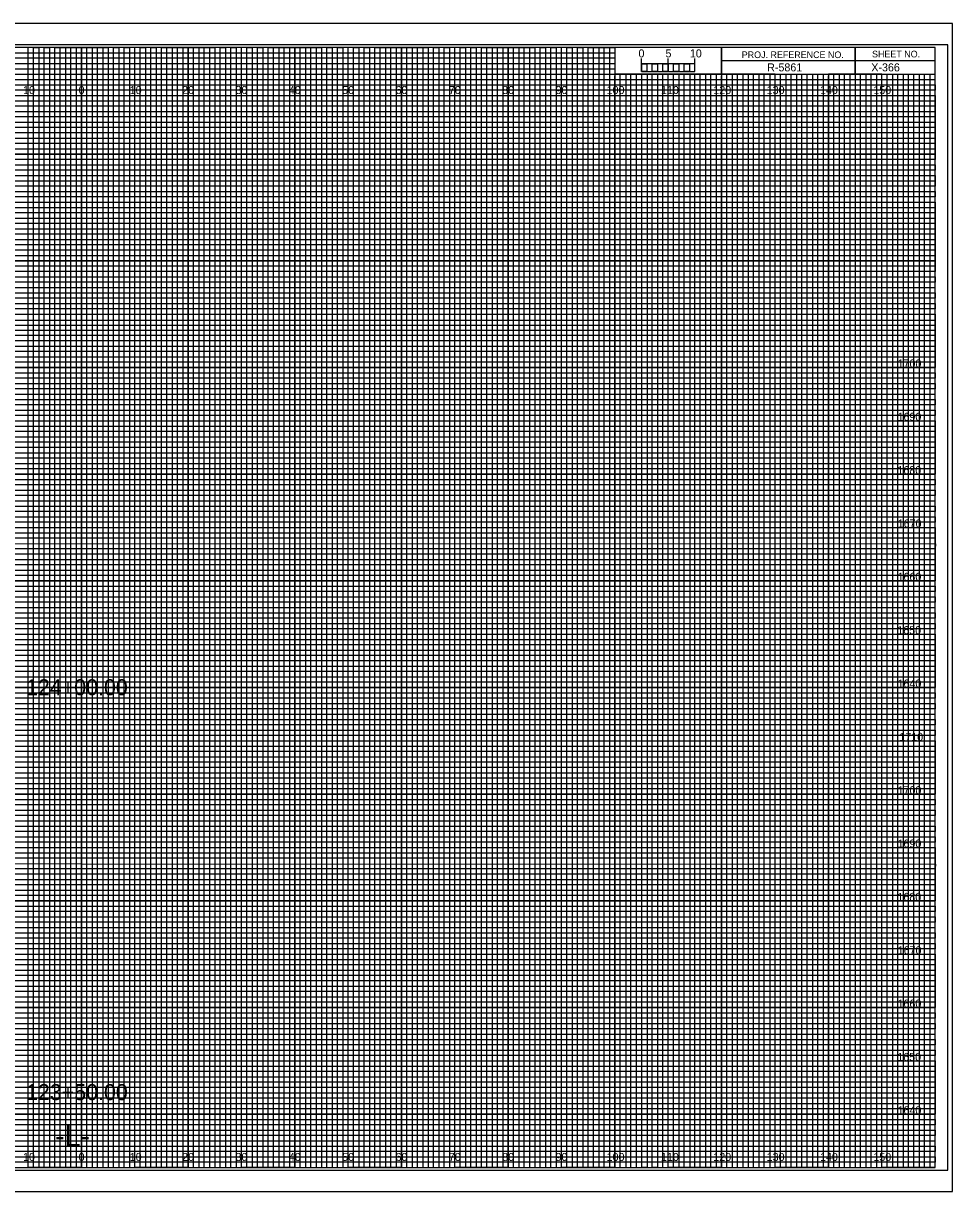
# Model space of a CAD drawing. Extents: x -13 to 323, y -5 to 2414.
# Drawn here: x 149.1 to 323.3, y 435.5 to 654.5 of the extents above; entities that cross this region are included whole.
import ezdxf

# ---------------------------------------------------------------- set-up
doc = ezdxf.new("R2010")
doc.units = 0
for name, color, linetype in [('Prop XS Alignment Label', 7, 'Continuous'), ('Prop XS Bar Scale Labels', 7, 'Continuous'), ('Prop XS Elevation Labels', 7, 'Continuous'), ('Prop XS Offset Labels', 7, 'Continuous'), ('Prop XS Project Number', 7, 'Continuous'), ('Prop XS Sheet Number', 7, 'Continuous'), ('Prop XS Station Labels', 7, 'Continuous'), ('Sheet Cross Section CELL', 7, 'Continuous'), ('Sheet Cross Section Grid Major CELL', 7, 'Continuous'), ('Sheet Cross Section Grid Middle CELL', 7, 'Continuous'), ('Sheet Cross Section Grid Minor 1 CELL', 7, 'Continuous'), ('Sheet Cross Section Grid Minor 2 CELL', 7, 'Continuous'), ('Sheet Cross Section Scale CELL', 7, 'Continuous'), ('Sheet Cutting Line CELL', 7, 'Continuous'), ('Sheet DOT Grid CELL', 7, 'Continuous'), ('Sheet Plot Border Inside CELL', 7, 'Continuous'), ('Sheet Plot Border Outside CELL', 7, 'Continuous')]:
    doc.layers.add(name, color=color, linetype=linetype)

msp = doc.modelspace()

# ---------------------------------------------------------------- linework, layer by layer
at = {"layer": 'Sheet Cross Section CELL'}
for p, q in [((305, 650), (305, 645)), ((305, 645), (305, 650)), ((280, 647.5), (280, 645)), ((320, 647.49), (280, 647.49)), ((280, 645), (320, 645))]:
    msp.add_line(p, q, dxfattribs=at)
for points in [[(320, 650), (0, 650), (0, 440), (320, 440)], [(280, 650), (260, 650), (260, 645.03), (280, 645.03)], [(320, 650), (280, 650), (280, 645), (320, 645)]]:
    msp.add_lwpolyline(points, close=True, dxfattribs=at)
at = {"layer": 'Sheet Cross Section Grid Major CELL'}
for p, q in [((150, 650), (140, 650)), ((150, 440), (150, 650)), ((170, 650), (160, 650)), ((160, 650), (160, 440)), ((170, 440), (170, 650)), ((190, 650), (180, 650)), ((180, 650), (180, 440)), ((190, 440), (190, 650)), ((210, 650), (200, 650)), ((200, 650), (200, 440)), ((210, 440), (210, 650)), ((230, 650), (220, 650)), ((220, 650), (220, 440)), ((230, 440), (230, 650)), ((250, 650), (240, 650)), ((240, 650), (240, 440)), ((250, 440), (250, 650)), ((260, 650), (260, 440)), ((270, 440), (270, 645)), ((290, 645), (280, 645)), ((280, 645), (280, 440)), ((290, 440), (290, 645)), ((310, 645), (300, 645)), ((300, 645), (300, 440)), ((310, 440), (310, 645)), ((160, 440), (150, 440)), ((180, 440), (170, 440)), ((200, 440), (190, 440)), ((220, 440), (210, 440)), ((240, 440), (230, 440)), ((260, 440), (250, 440)), ((280, 440), (270, 440)), ((300, 440), (290, 440)), ((320, 440), (310, 440)), ((320, 440), (320, 440))]:
    msp.add_line(p, q, dxfattribs=at)
for points in [[(0, 640), (320, 640), (320, 630), (0, 630)], [(0, 620), (320, 620), (320, 610), (0, 610)], [(0, 600), (320, 600), (320, 590), (0, 590)], [(0, 580), (320, 580), (320, 570), (0, 570)], [(0, 560), (320, 560), (320, 550), (0, 550)], [(0, 540), (320, 540), (320, 530), (0, 530)], [(0, 520), (320, 520), (320, 510), (0, 510)], [(0, 500), (320, 500), (320, 490), (0, 490)], [(0, 480), (320, 480), (320, 470), (0, 470)], [(0, 460), (320, 460), (320, 450), (0, 450)]]:
    msp.add_lwpolyline(points, dxfattribs=at)
at = {"layer": 'Sheet Cross Section Grid Middle CELL'}
for points in [[(145, 440), (155, 440), (155, 650), (165, 650), (165, 440), (175, 440), (175, 650), (185, 650), (185, 440), (195, 440), (195, 650), (205, 650), (205, 440), (215, 440), (215, 650), (225, 650), (225, 440), (235, 440), (235, 650), (245, 650), (245, 440), (255, 440), (255, 650), (259.93, 650), (260, 650), (260, 645), (264.99, 645), (264.99, 440), (275, 440), (275, 645), (285, 645), (285, 440), (295, 440), (295, 645), (305, 645), (305, 440), (315, 440), (315, 645)], [(0, 645), (275, 645)], [(0, 625), (320, 625), (320, 635), (0, 635)], [(0, 605), (320, 605), (320, 615), (0, 615)], [(0, 585), (320, 585), (320, 595), (0, 595)], [(0, 565), (320, 565), (320, 575), (0, 575)], [(0, 545), (320, 545), (320, 555), (0, 555)], [(0, 525), (320, 525), (320, 535), (0, 535)], [(0, 505), (320, 505), (320, 515), (0, 515)], [(0, 485), (320, 485), (320, 495), (0, 495)], [(0, 465), (320, 465), (320, 475), (0, 475)], [(0, 445), (320, 445), (320, 455), (0, 455)]]:
    msp.add_lwpolyline(points, dxfattribs=at)
at = {"layer": 'Sheet Cross Section Grid Minor 1 CELL'}
for p, q in [((0, 649), (260, 649)), ((260, 649), (260, 647.98)), ((260, 647.98), (0, 647.98)), ((0, 647), (260, 647)), ((260, 647), (260, 645.89)), ((260, 645.89), (0, 645.89)), ((0, 644), (320, 644))]:
    msp.add_line(p, q, dxfattribs=at)
for points in [[(0, 643), (270, 643), (320, 643), (320, 642), (0, 642)], [(0, 641), (320, 641), (320, 639), (0, 639)], [(0, 638), (320, 638), (320, 637), (0, 636.98)], [(0, 636), (320, 636), (320, 634), (0, 634)], [(0, 633), (320, 633), (320, 632), (0, 632)], [(0, 631), (320, 631), (320, 629), (0, 629)], [(0, 628), (320, 628), (320, 627), (0, 627)], [(0, 626), (320, 626), (320, 624), (0, 624)], [(0, 623), (320, 623), (320, 622), (0, 622)], [(0, 621), (320, 621), (320, 619), (0, 619)], [(0, 618), (320, 618), (320, 617), (0, 617)], [(0, 616), (320, 616), (320, 613.95), (320, 613), (320, 612), (0, 612)], [(0, 614), (320, 614), (320, 613), (0, 613)], [(0, 611), (320, 611), (320, 609), (0, 609.03)], [(0, 609.03), (320, 609), (320, 608), (0, 608)], [(0, 607), (320, 607), (320, 606), (0, 606)], [(0, 604), (320, 604), (320, 603), (0, 603)], [(0, 602), (320, 602), (320, 601), (0, 601)], [(-0.07, 598.89), (320, 598.89), (320, 597.88), (-0.07, 597.88)], [(0, 597), (320, 597), (320, 596), (0, 596)], [(0, 594), (320, 594), (320, 593), (0, 593)], [(0, 592), (320, 592), (320, 591), (0, 591)], [(0, 589), (320, 589), (320, 588), (0, 588)], [(0, 587), (320, 587), (320, 586), (0, 586)], [(0, 584), (320, 584), (320, 583), (0, 583)], [(0, 582), (320, 582), (320, 581), (0, 581)], [(0, 579), (320, 579), (319.99, 577.98), (0, 578)], [(0, 577), (320, 577), (320, 576), (0, 576)], [(0, 574), (320, 574), (320, 573), (0, 573)], [(0, 572), (320, 572), (320, 571), (0, 571)], [(0, 569), (320, 569), (320, 568), (0, 568)], [(0, 567), (320, 567), (320, 566), (0, 566)], [(0, 564), (320, 564), (320, 563), (0, 563)], [(0, 562), (320, 562), (320, 561), (0, 561)], [(0, 559), (320, 559), (320, 558), (0, 558)], [(0, 556.99), (320.07, 556.91), (320, 556), (0, 556)], [(0, 554), (320, 554), (320, 553), (0, 553)], [(0, 552), (320, 552), (320, 551), (0, 551)], [(0, 549), (320, 549), (320, 548), (0, 548)], [(0, 547), (320, 547), (320, 546), (0, 546)], [(0, 544), (320, 544), (320, 543), (0, 543)], [(0, 542), (320, 542), (320, 541), (0, 541)], [(0, 539), (320, 539), (320, 538), (0, 538)], [(0, 537), (320, 537), (320, 536), (0, 536)], [(0, 534), (320, 534), (320, 533), (0, 533)], [(0, 532), (320, 532), (320, 531), (0, 531)], [(0, 529), (320, 529), (320, 528), (0, 528)], [(0, 527), (320, 527), (320, 526), (0, 526)], [(0, 524), (320, 524), (320, 523), (0, 523)], [(0, 522), (320, 522), (320, 521), (0, 521)], [(0, 519), (320, 519), (319.99, 517.98), (0, 518)], [(0, 517), (320, 517), (320, 516), (0, 516)], [(0, 514), (320, 514), (320, 513), (0, 513)], [(0, 512), (320, 512), (320, 511), (0, 511)], [(0, 509), (320, 509), (320, 508), (0, 508)], [(0, 507), (320, 507), (320, 506), (0, 506)], [(0, 504), (320, 504), (320, 503), (0, 503)], [(0, 502), (320, 502), (320, 501), (0, 501)], [(0, 499), (320, 499), (320, 498), (0, 498)], [(0, 496.99), (320.07, 496.91), (320, 496), (0, 496)], [(0, 494), (320, 494), (320, 493), (0, 493)], [(0, 492), (320, 492), (320, 491), (0, 491)], [(0, 489), (320, 489), (320, 488), (0, 488)], [(0, 487), (320, 487), (320, 486), (0, 486)], [(0, 484), (320, 484), (320, 483), (0, 483)], [(0, 482), (320, 482), (320, 481), (0, 481)], [(0, 479), (320, 479), (320, 478), (0, 478)], [(0, 477), (320, 477), (320, 476), (0, 476)], [(0, 474), (320, 474), (320, 473), (0, 473)], [(0, 472), (320, 472), (320, 471), (0, 471)], [(0, 469), (320, 469), (320, 468), (0, 468)], [(0, 467), (320, 467), (320, 466), (0, 466)], [(0, 464), (320, 464), (320, 463), (0, 463)], [(0, 462), (320, 462), (320, 461), (0, 461)], [(0, 459), (320, 459), (320, 458), (0, 458)], [(0, 457), (320, 457), (320, 456), (0, 456)], [(0, 454), (320, 454), (320, 453), (0, 453)], [(0, 452), (320, 452), (320, 451), (0, 451)], [(0, 449), (320, 449), (320, 448), (0, 448)], [(0, 447), (320, 447), (320, 446), (0, 446)], [(0, 444), (320, 444), (320, 443), (0, 443)], [(0, 442), (320, 442), (320, 441), (0, 441)]]:
    msp.add_lwpolyline(points, dxfattribs=at)
at = {"layer": 'Sheet Cross Section Grid Minor 2 CELL'}
for p, q in [((267, 645), (266.01, 645)), ((266.01, 645), (266.01, 440)), ((267, 440), (267, 645)), ((269, 645), (268, 645)), ((268, 645), (268, 440)), ((269, 440), (269, 645)), ((266.01, 440), (265, 440)), ((268, 440), (267, 440))]:
    msp.add_line(p, q, dxfattribs=at)
for points in [[(150, 440), (151, 440), (151, 650), (152, 650), (152, 440)], [(152, 440), (153, 440), (153, 650), (154, 650), (154, 440)], [(155, 440), (156, 440), (156, 650), (157, 650), (157, 440)], [(157, 440), (158, 440), (158, 650), (159, 650), (159, 440)], [(160, 440), (161, 440), (161, 650), (162, 650), (162, 440)], [(162, 440), (163, 440), (163, 650), (164, 650), (164, 440)], [(165, 440), (166, 440), (166, 650), (167, 650), (167, 440)], [(167, 440), (168, 440), (168, 650), (169, 650), (169, 440)], [(170, 440), (171, 440), (171, 650), (172, 650), (172, 440)], [(172, 440), (173, 440), (173, 650), (174, 650), (174, 440)], [(175, 440), (176, 440), (176, 650), (177, 650), (177, 440)], [(177, 440), (178, 440), (178, 650), (179, 650), (179, 440)], [(180, 440), (181, 440), (181, 650), (182, 650), (182, 440)], [(182, 440), (183, 440), (183, 650), (184, 650), (184, 440)], [(185, 440), (186, 440), (186, 650), (187, 650), (187, 440)], [(187, 440), (188, 440), (188, 650), (189, 650), (189, 440)], [(190, 440), (191, 440), (191, 650), (192, 650), (192, 440)], [(192, 440), (193, 440), (193, 650), (194, 650), (194, 440)], [(195, 440), (196, 440), (196, 650), (197, 650), (197, 440)], [(197, 440), (198, 440), (198, 650), (199, 650), (199, 440)], [(200, 440), (201, 440), (201, 650), (202, 650), (202, 440)], [(202, 440), (203, 440), (203, 650), (204, 650), (204, 440)], [(205, 440), (206, 440), (206, 650), (207, 650), (207, 440)], [(207, 440), (208, 440), (208, 650), (209, 650), (209, 440)], [(210, 440), (211, 440), (211, 650), (212, 650), (212, 440)], [(212, 440), (213, 440), (213, 650), (214, 650), (214, 440)], [(215, 440), (216, 440), (216, 650), (217, 650), (217, 440)], [(217, 440), (218, 440), (218, 650), (219, 650), (219, 440)], [(220, 440), (221, 440), (221, 650), (222, 650), (222, 440)], [(222, 440), (223, 440), (223, 650), (224, 650), (224, 440)], [(225, 440), (226, 440), (226, 650), (227, 650), (227, 440)], [(227, 440), (228, 440), (228, 650), (229, 650), (229, 440)], [(230, 440), (231, 440), (231, 650), (232, 650), (232, 440)], [(232, 440), (233, 440), (233, 650), (234, 650), (234, 440)], [(235, 440), (236, 440), (236, 650), (237, 650), (237, 440)], [(237, 440), (238, 440), (238, 650), (239, 650), (239, 440)], [(240, 440), (241, 440), (241, 650), (242, 650), (242, 440)], [(242, 440), (243, 440), (243, 650), (244, 650), (244, 440)], [(245, 440), (246, 440), (246, 650), (247, 650), (247, 440)], [(247, 440), (248, 440), (248, 650), (249, 650), (249, 440)], [(250, 440), (251, 440), (251, 650), (252, 650), (252, 440)], [(252, 440), (253, 440), (253, 650), (254, 650), (254, 440)], [(255, 440), (256, 440), (256, 650), (257, 650), (257, 440)], [(257, 440), (258, 440), (258, 650), (259, 650), (259, 440)], [(260, 440), (261, 440), (261, 645), (262.02, 645), (262.02, 440)], [(262, 440), (263, 440), (263, 645), (263.99, 645), (263.99, 440)], [(270, 440), (270.98, 440), (270.98, 645), (272, 645), (272, 440)], [(272, 440), (273, 440), (273, 645), (274.05, 645), (274.05, 440)], [(275, 440), (276, 440), (276, 645), (277, 645), (277, 440)], [(277, 440), (278, 440), (278, 645), (279, 645), (279, 440)], [(280, 440), (281, 440), (281, 645), (282, 645), (282, 440)], [(282, 440), (283, 440), (283, 645), (284, 645), (284, 440)], [(285, 440), (286, 440), (286, 645), (287, 645), (287, 440)], [(287, 440), (288, 440), (288, 645), (289, 645), (289, 440)], [(290, 440), (291, 440), (291, 645), (292, 645), (292, 440)], [(292, 440), (293, 440), (293, 645), (294, 645), (294, 440)], [(295, 440), (296, 440), (296, 645), (297, 645), (297, 440)], [(297, 440), (298, 440), (298, 645), (299, 645), (299, 440)], [(300, 440), (301, 440), (301, 645), (302, 645), (302, 440)], [(302, 440), (303, 440), (303, 645), (304, 645), (304, 440)], [(305, 440), (306, 440), (306, 645), (307, 645), (307, 440)], [(307, 440), (308, 440), (308, 645), (309, 645), (309, 440)], [(310, 440), (311, 440), (311, 645), (312, 645), (312, 440)], [(312, 440), (313, 440), (313, 645), (314, 645), (314, 440)], [(315, 440), (316, 440), (316, 645), (317, 645), (317, 440)], [(317, 440), (318, 440), (318, 645), (319, 645), (319, 440)]]:
    msp.add_lwpolyline(points, dxfattribs=at)
at = {"layer": 'Sheet Cross Section Scale CELL'}
for p, q in [((265, 645.49), (265, 647.9)), ((265, 646.9), (265, 647.9)), ((270, 645.49), (270, 647.9)), ((275, 645.49), (275, 647.9)), ((275, 646.9), (275, 647.9))]:
    msp.add_line(p, q, dxfattribs=at)
for points in [[(275, 646.9), (265, 646.9), (265, 645.49), (275, 645.49)], [(265, 646.9), (266, 646.9), (266, 645.49), (265, 645.49)], [(267, 646.9), (268, 646.9), (268, 645.49), (267, 645.49)], [(269, 646.9), (270, 646.9), (270, 645.49), (269, 645.49)], [(271, 646.9), (272, 646.9), (272, 645.49), (271, 645.49)], [(273, 646.9), (274, 646.9), (274, 645.49), (273, 645.49)]]:
    msp.add_lwpolyline(points, close=True, dxfattribs=at)
at = {"layer": 'Sheet Cutting Line CELL'}
for p, q in [((323.3, 654.5), (-13.4, 654.5)), ((-13.4, 435.5), (323.3, 435.5))]:
    msp.add_line(p, q, dxfattribs=at)
at = {"layer": 'Sheet DOT Grid CELL'}
for p, q in [((150, 440), (150, 650)), ((160, 440), (160, 650)), ((170, 440), (170, 650)), ((180, 440), (180, 650)), ((190, 440), (190, 650)), ((200, 440), (200, 650)), ((210, 440), (210, 650)), ((220, 440), (220, 650)), ((230, 440), (230, 650)), ((240, 440), (240, 650)), ((250, 440), (250, 650)), ((260, 440), (260, 644.69)), ((270, 440), (270, 644.69)), ((280, 440), (280, 644.69)), ((290, 440), (290, 644.69)), ((300, 440), (300, 644.69)), ((310, 440), (310, 644.69)), ((0, 640), (320, 640)), ((0, 630), (320, 630)), ((0, 620), (320, 620)), ((0, 610), (320, 610)), ((0, 600), (320, 600)), ((0, 590), (320, 590)), ((0, 580), (320, 580)), ((0, 570), (320, 570)), ((0, 560), (320, 560)), ((0, 550), (320, 550)), ((0, 540), (320, 540)), ((0, 530), (320, 530)), ((0, 520), (320, 520)), ((0, 510), (320, 510)), ((0, 500), (320, 500)), ((0, 490), (320, 490)), ((0, 480), (320, 480)), ((0, 470), (320, 470)), ((0, 460), (320, 460)), ((0, 450), (320, 450))]:
    msp.add_line(p, q, dxfattribs=at)
at = {"layer": 'Sheet Plot Border Inside CELL'}
msp.add_lwpolyline([(-10.8, 439.5), (322.4, 439.5), (322.4, 650.5), (-10.8, 650.5)], close=True, dxfattribs=at)
at = {"layer": 'Sheet Plot Border Outside CELL'}
msp.add_lwpolyline([(-13.4, 435.5), (323.3, 435.5), (323.3, 654.5), (-13.4, 654.5)], close=True, dxfattribs=at)

# ---------------------------------------------------------------- texts
at = {"layer": 'Prop XS Alignment Label'}
msp.add_text('-L-', height=4, dxfattribs=at).set_placement((155.06, 444))
at = {"layer": 'Prop XS Bar Scale Labels'}
for s, p in [('5', (269.47, 648.12)), ('10', (274.04, 648.12))]:
    msp.add_text(s, height=1.5, dxfattribs=at).set_placement(p)
at = {"layer": 'Prop XS Elevation Labels'}
for s, p in [('1700', (312.98, 590)), ('1690', (312.97, 580)), ('1680', (312.95, 570)), ('1670', (313, 560)), ('1660', (312.97, 550)), ('1650', (312.92, 540)), ('1640', (312.97, 530)), ('1710', (313.31, 520)), ('1700', (312.98, 510)), ('1690', (312.97, 500)), ('1680', (312.95, 490)), ('1670', (313, 480)), ('1660', (312.97, 470)), ('1650', (312.92, 460)), ('1640', (312.97, 450))]:
    msp.add_text(s, height=1.5, dxfattribs=at).set_placement(p)
at = {"layer": 'Prop XS Offset Labels'}
for s, p in [('10', (149.04, 641.25)), ('0', (159.45, 641.25)), ('0', (159.45, 641.25)), ('10', (169.04, 641.25)), ('20', (178.86, 641.25)), ('30', (188.86, 641.25)), ('40', (198.86, 641.25)), ('50', (208.86, 641.25)), ('60', (218.86, 641.25)), ('70', (228.86, 641.25)), ('80', (238.86, 641.25)), ('90', (248.86, 641.25)), ('100', (258.44, 641.25)), ('110', (268.62, 641.25)), ('120', (278.44, 641.25)), ('130', (288.44, 641.25)), ('140', (298.44, 641.25)), ('150', (308.44, 641.25)), ('10', (149.04, 441.25)), ('0', (159.45, 441.25)), ('0', (159.45, 441.25)), ('10', (169.04, 441.25)), ('20', (178.86, 441.25)), ('30', (188.86, 441.25)), ('40', (198.86, 441.25)), ('50', (208.86, 441.25)), ('60', (218.86, 441.25)), ('70', (228.86, 441.25)), ('80', (238.86, 441.25)), ('90', (248.86, 441.25)), ('100', (258.44, 441.25)), ('110', (268.62, 441.25)), ('120', (278.44, 441.25)), ('130', (288.44, 441.25)), ('140', (298.44, 441.25)), ('150', (308.44, 441.25))]:
    msp.add_text(s, height=1.5, dxfattribs=at).set_placement(p)
at = {"layer": 'Prop XS Project Number'}
msp.add_text('R-5861', height=1.5, dxfattribs=at).set_placement((288.53, 645.5))
at = {"layer": 'Prop XS Sheet Number'}
msp.add_text('X-366', height=1.5, dxfattribs=at).set_placement((308.05, 645.5))
at = {"layer": 'Prop XS Station Labels'}
for s, p in [('124+00.00', (149.59, 528.55)), ('123+50.00', (149.59, 452.65))]:
    msp.add_text(s, height=3, dxfattribs=at).set_placement(p)
at = {"layer": 'Sheet Cross Section CELL'}
for s, p in [('PROJ. REFERENCE NO.', (283.77, 647.99)), ('SHEET NO.', (308.19, 648.12))]:
    msp.add_text(s, height=1.25, dxfattribs=at).set_placement(p)
at = {"layer": 'Sheet Cross Section Scale CELL'}
msp.add_text('0', height=1.5, dxfattribs=at).set_placement((264.41, 648.12))

doc.saveas('drawing.dxf')
